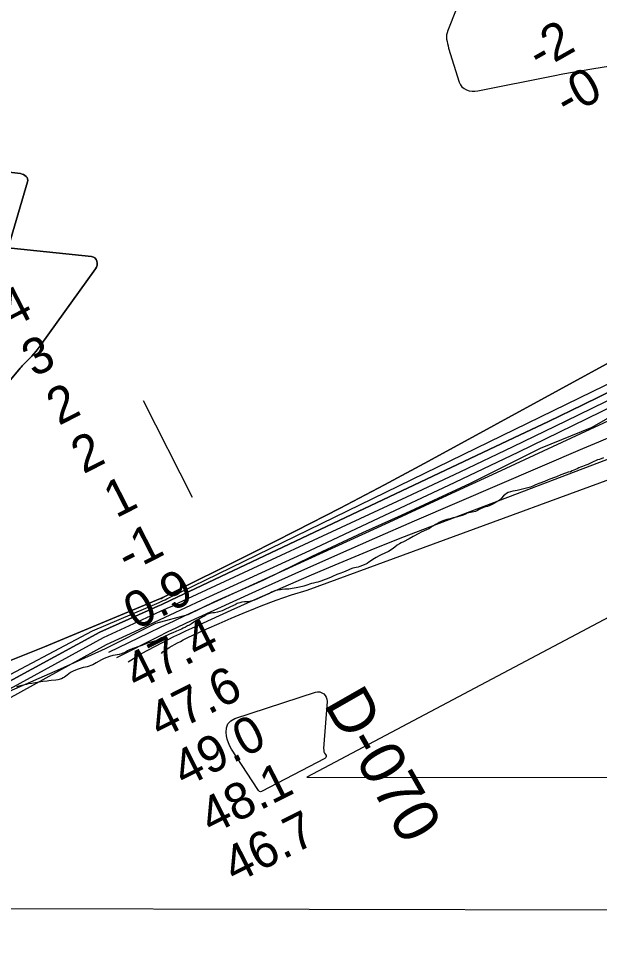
# Model space of a CAD drawing. Extents: x 3177385 to 3215275, y 903885 to 929304.
# Drawn here: x 3190624 to 3191696, y 909264 to 910956 of the extents above; entities that cross this region are included whole.
import ezdxf

# ---------------------------------------------------------------- set-up
doc = ezdxf.new("R2010")
doc.units = 0
for name, color, linetype in [('V-GRID-FRAM', 7, 'Continuous'), ('V-RIVR-EDGE', 7, 'Continuous'), ('V-RIVR-RANG', 7, 'Continuous'), ('V-RIVR-RANG-IDEN', 7, 'Continuous'), ('V-SITE-VEGE', 7, 'Continuous'), ('V-TOPO-BNDY', 7, 'Continuous'), ('V-TOPO-DPTH', 7, 'Continuous'), ('V-TOPO-MAJR', 7, 'Continuous'), ('V-TOPO-MINR', 7, 'Continuous'), ('V-TOPO-WATR', 7, 'Continuous')]:
    doc.layers.add(name, color=color, linetype=linetype)

msp = doc.modelspace()

# ---------------------------------------------------------------- linework, layer by layer
at = {"layer": 'V-GRID-FRAM'}
msp.add_lwpolyline([(3181653.7, 927525.9), (3181603.5, 909337.1), (3212939.2, 909264.2), (3212973.6, 927453), (3181653.7, 927525.9)], dxfattribs=at)
at = {"layer": 'V-RIVR-EDGE'}
msp.add_lwpolyline([(3190607.3, 909716.4), (3190701.7, 909757.9), (3190784.4, 909795), (3190877.1, 909841.8), (3190936.7, 909857.7), (3190985.9, 909881.5), (3191075.1, 909921.2), (3191165.2, 909965.4), (3191259.2, 910008.6), (3191330.1, 910041), (3191457.2, 910099.8), (3191586.4, 910164.3), (3191682.1, 910203.2), (3191755.7, 910245.6)], dxfattribs=at)
at = {"layer": 'V-RIVR-RANG'}
msp.add_line((3190945, 910073.2), (3190854.6, 910251.6), dxfattribs=at)
at = {"layer": 'V-SITE-VEGE'}
for p, q in [((3191684.8, 910139.7), (3191673.8, 910134)), ((3191688.1, 910141.1), (3191684.8, 910139.7)), ((3191691.7, 910142.6), (3191688.1, 910141.1)), ((3191695.6, 910143.6), (3191691.7, 910142.6)), ((3191702.9, 910146.5), (3191695.6, 910143.6)), ((3191632.8, 910118.1), (3191624.2, 910114.8)), ((3191637.5, 910119.7), (3191632.8, 910118.1)), ((3191641.6, 910120.9), (3191637.5, 910119.7)), ((3191644.9, 910122.2), (3191641.6, 910120.9)), ((3191654, 910126.1), (3191644.9, 910122.2)), ((3191657.1, 910127.8), (3191654, 910126.1)), ((3191660.4, 910129.3), (3191657.1, 910127.8)), ((3191664.1, 910130.5), (3191660.4, 910129.3)), ((3191670.1, 910133), (3191664.1, 910130.5)), ((3191671.8, 910133.4), (3191670.1, 910133)), ((3191673.8, 910134), (3191671.8, 910133.4)), ((3191593.9, 910102.7), (3191585.3, 910099.6)), ((3191600.9, 910105.9), (3191593.9, 910102.7)), ((3191604, 910106.9), (3191600.9, 910105.9)), ((3191612.4, 910110.2), (3191604, 910106.9)), ((3191616.3, 910111.4), (3191612.4, 910110.2)), ((3191624.2, 910114.8), (3191616.3, 910111.4)), ((3191535.8, 910084.8), (3191527, 910082.3)), ((3191540, 910085.8), (3191535.8, 910084.8)), ((3191543.5, 910086.3), (3191540, 910085.8)), ((3191551, 910088.2), (3191543.5, 910086.3)), ((3191567.9, 910092.6), (3191551, 910088.2)), ((3191573.4, 910094.7), (3191567.9, 910092.6)), ((3191577.6, 910096.5), (3191573.4, 910094.7)), ((3191585.3, 910099.6), (3191577.6, 910096.5)), ((3191509.2, 910067.4), (3191505, 910064.9)), ((3191511.9, 910069.3), (3191509.2, 910067.4)), ((3191514.8, 910072.1), (3191511.9, 910069.3)), ((3191518.4, 910076.2), (3191514.8, 910072.1)), ((3191520.8, 910078.5), (3191518.4, 910076.2)), ((3191523.7, 910080.7), (3191520.8, 910078.5)), ((3191527, 910082.3), (3191523.7, 910080.7)), ((3191473.5, 910050.9), (3191470.6, 910049.2)), ((3191481.2, 910054.7), (3191473.5, 910050.9)), ((3191485.2, 910055.9), (3191481.2, 910054.7)), ((3191488.5, 910056.7), (3191485.2, 910055.9)), ((3191497.5, 910060.7), (3191488.5, 910056.7)), ((3191505, 910064.9), (3191497.5, 910060.7)), ((3191413.7, 910033), (3191406.3, 910030.5)), ((3191420.1, 910034.2), (3191413.7, 910033)), ((3191425.2, 910035.8), (3191420.1, 910034.2)), ((3191426.9, 910036), (3191425.2, 910035.8)), ((3191431.3, 910037), (3191426.9, 910036)), ((3191437.5, 910038.8), (3191431.3, 910037)), ((3191444, 910040.9), (3191437.5, 910038.8)), ((3191448, 910042.5), (3191444, 910040.9)), ((3191451.5, 910044.2), (3191448, 910042.5)), ((3191463.4, 910047), (3191451.5, 910044.2)), ((3191466.9, 910047.6), (3191463.4, 910047)), ((3191470.6, 910049.2), (3191466.9, 910047.6)), ((3191381.7, 910016.4), (3191379.1, 910014.9)), ((3191385.5, 910019), (3191381.7, 910016.4)), ((3191389.3, 910021.1), (3191385.5, 910019)), ((3191393, 910023.6), (3191389.3, 910021.1)), ((3191395.7, 910025.1), (3191393, 910023.6)), ((3191399.9, 910027), (3191395.7, 910025.1)), ((3191403.6, 910028.8), (3191399.9, 910027)), ((3191406.3, 910030.5), (3191403.6, 910028.8)), ((3191351.7, 910001.3), (3191344.2, 909996.9)), ((3191361.9, 910007), (3191351.7, 910001.3)), ((3191366.7, 910009.5), (3191361.9, 910007)), ((3191376.2, 910013.9), (3191366.7, 910009.5)), ((3191379.1, 910014.9), (3191376.2, 910013.9)), ((3191322.5, 909985.6), (3191317.7, 909982)), ((3191326.5, 909987.7), (3191322.5, 909985.6)), ((3191329.6, 909989.6), (3191326.5, 909987.7)), ((3191333.6, 909991.5), (3191329.6, 909989.6)), ((3191344.2, 909996.9), (3191333.6, 909991.5)), ((3191288.9, 909966), (3191283.2, 909962.8)), ((3191292.9, 909967.9), (3191288.9, 909966)), ((3191299.3, 909970.6), (3191292.9, 909967.9)), ((3191306.1, 909973.9), (3191299.3, 909970.6)), ((3191313, 909978.4), (3191306.1, 909973.9)), ((3191317.7, 909982), (3191313, 909978.4)), ((3191264.4, 909950.6), (3191253.4, 909946)), ((3191267.2, 909952), (3191264.4, 909950.6)), ((3191270.1, 909953.9), (3191267.2, 909952)), ((3191272.8, 909956.1), (3191270.1, 909953.9)), ((3191277.4, 909959.2), (3191272.8, 909956.1)), ((3191280.3, 909961.1), (3191277.4, 909959.2)), ((3191283.2, 909962.8), (3191280.3, 909961.1)), ((3191210.9, 909931.6), (3191202.7, 909927.9)), ((3191216.2, 909933.5), (3191210.9, 909931.6)), ((3191223.4, 909935.7), (3191216.2, 909933.5)), ((3191227.8, 909937.4), (3191223.4, 909935.7)), ((3191231.8, 909939.5), (3191227.8, 909937.4)), ((3191235.3, 909941.1), (3191231.8, 909939.5)), ((3191240.6, 909943), (3191235.3, 909941.1)), ((3191243.7, 909943.6), (3191240.6, 909943)), ((3191246.6, 909944.6), (3191243.7, 909943.6)), ((3191250.1, 909945.2), (3191246.6, 909944.6)), ((3191253.4, 909946), (3191250.1, 909945.2)), ((3191164.5, 909914.9), (3191153.9, 909911.2)), ((3191167.8, 909915.5), (3191164.5, 909914.9)), ((3191172.1, 909916.7), (3191167.8, 909915.5)), ((3191175.7, 909917.5), (3191172.1, 909916.7)), ((3191179.6, 909918.7), (3191175.7, 909917.5)), ((3191183.4, 909919.8), (3191179.6, 909918.7)), ((3191187.8, 909921.6), (3191183.4, 909919.8)), ((3191191.3, 909922.9), (3191187.8, 909921.6)), ((3191199, 909926), (3191191.3, 909922.9)), ((3191202.7, 909927.9), (3191199, 909926)), ((3191090.5, 909898.8), (3191086.8, 909896.7)), ((3191093.6, 909900.3), (3191090.5, 909898.8)), ((3191098.2, 909901.7), (3191093.6, 909900.3)), ((3191102.4, 909902.3), (3191098.2, 909901.7)), ((3191107, 909903), (3191102.4, 909902.3)), ((3191110.3, 909903.8), (3191107, 909903)), ((3191114.9, 909904.4), (3191110.3, 909903.8)), ((3191119.5, 909904.7), (3191114.9, 909904.4)), ((3191122.5, 909904.7), (3191119.5, 909904.7)), ((3191128.9, 909905.4), (3191122.5, 909904.7)), ((3191135.7, 909906.6), (3191128.9, 909905.4)), ((3191139.2, 909907.6), (3191135.7, 909906.6)), ((3191142.3, 909908.2), (3191139.2, 909907.6)), ((3191150.4, 909910.2), (3191142.3, 909908.2)), ((3191153.9, 909911.2), (3191150.4, 909910.2)), ((3191040.4, 909880.9), (3191036, 909880.3)), ((3191048.9, 909881.1), (3191040.4, 909880.9)), ((3191052.4, 909882.1), (3191048.9, 909881.1)), ((3191059, 909884.4), (3191052.4, 909882.1)), ((3191065.8, 909887.1), (3191059, 909884.4)), ((3191079.7, 909893.1), (3191065.8, 909887.1)), ((3191082.4, 909894.6), (3191079.7, 909893.1)), ((3191086.8, 909896.7), (3191082.4, 909894.6)), ((3190999.4, 909864.7), (3190995, 909863.5)), ((3191005.4, 909867.6), (3190999.4, 909864.7)), ((3191020.6, 909874.1), (3191005.4, 909867.6)), ((3191023.7, 909875.6), (3191020.6, 909874.1)), ((3191027, 909877.7), (3191023.7, 909875.6)), ((3191031.8, 909879.5), (3191027, 909877.7)), ((3191036, 909880.3), (3191031.8, 909879.5)), ((3190953, 909847.4), (3190949.4, 909845)), ((3190960.5, 909851.8), (3190953, 909847.4)), ((3190963.6, 909853.3), (3190960.5, 909851.8)), ((3190966.7, 909854.9), (3190963.6, 909853.3)), ((3190970.9, 909857.5), (3190966.7, 909854.9)), ((3190974.4, 909858.9), (3190970.9, 909857.5)), ((3190978.6, 909859.9), (3190974.4, 909858.9)), ((3190982.5, 909860.7), (3190978.6, 909859.9)), ((3190985.6, 909860.9), (3190982.5, 909860.7)), ((3190991.1, 909862.1), (3190985.6, 909860.9)), ((3190995, 909863.5), (3190991.1, 909862.1)), ((3190924.4, 909830.9), (3190915.4, 909827.2)), ((3190927.5, 909832.6), (3190924.4, 909830.9)), ((3190931.9, 909834.5), (3190927.5, 909832.6)), ((3190935.7, 909836.6), (3190931.9, 909834.5)), ((3190939.2, 909838.3), (3190935.7, 909836.6)), ((3190943.2, 909840.4), (3190939.2, 909838.3)), ((3190949.4, 909845), (3190943.2, 909840.4)), ((3190887.6, 909814.7), (3190881.7, 909811.3)), ((3190890.5, 909816.2), (3190887.6, 909814.7)), ((3190894.2, 909817.8), (3190890.5, 909816.2)), ((3190898.9, 909819.7), (3190894.2, 909817.8)), ((3190902.6, 909821.6), (3190898.9, 909819.7)), ((3190909.5, 909824.7), (3190902.6, 909821.6)), ((3190912.8, 909825.7), (3190909.5, 909824.7)), ((3190915.4, 909827.2), (3190912.8, 909825.7)), ((3190839, 909796.1), (3190835, 909794.8)), ((3190842.3, 909797.5), (3190839, 909796.1)), ((3190851.1, 909800.8), (3190842.3, 909797.5)), ((3190855.5, 909802.3), (3190851.1, 909800.8)), ((3190863.8, 909805.4), (3190855.5, 909802.3)), ((3190877.5, 909809.4), (3190863.8, 909805.4)), ((3190881.7, 909811.3), (3190877.5, 909809.4)), ((3190791.9, 909780.5), (3190787.1, 909778.8)), ((3190798.1, 909782.1), (3190791.9, 909780.5)), ((3190802.2, 909782.7), (3190798.1, 909782.1)), ((3190805.7, 909783.5), (3190802.2, 909782.7)), ((3190809.7, 909784), (3190805.7, 909783.5)), ((3190813.8, 909785), (3190809.7, 909784)), ((3190816.5, 909786.5), (3190813.8, 909785)), ((3190820.5, 909787.9), (3190816.5, 909786.5)), ((3190825.1, 909790.7), (3190820.5, 909787.9)), ((3190828.4, 909792.4), (3190825.1, 909790.7)), ((3190832.2, 909793.6), (3190828.4, 909792.4)), ((3190835, 909794.8), (3190832.2, 909793.6)), ((3190761.2, 909765.2), (3190750.5, 909761.5)), ((3190767.2, 909768.6), (3190761.2, 909765.2)), ((3190776.7, 909774.5), (3190767.2, 909768.6)), ((3190782, 909776.5), (3190776.7, 909774.5)), ((3190787.1, 909778.8), (3190782, 909776.5)), ((3190713.7, 909746.1), (3190708.8, 909742.3)), ((3190719.6, 909750.6), (3190713.7, 909746.1)), ((3190722.3, 909752.3), (3190719.6, 909750.6)), ((3190725.8, 909753.9), (3190722.3, 909752.3)), ((3190733.8, 909757.3), (3190725.8, 909753.9)), ((3190743.2, 909759.9), (3190733.8, 909757.3)), ((3190747.4, 909760.9), (3190743.2, 909759.9)), ((3190750.5, 909761.5), (3190747.4, 909760.9)), ((3190638.6, 909728.9), (3190624.6, 909725.7)), ((3190641.5, 909730), (3190638.6, 909728.9)), ((3190648.3, 909730.7), (3190641.5, 909730)), ((3190651.3, 909731.3), (3190648.3, 909730.7)), ((3190655, 909731.6), (3190651.3, 909731.3)), ((3190659.2, 909732.6), (3190655, 909731.6)), ((3190662.3, 909733), (3190659.2, 909732.6)), ((3190665.4, 909733.8), (3190662.3, 909733)), ((3190669.1, 909734.4), (3190665.4, 909733.8)), ((3190677, 909735.1), (3190669.1, 909734.4)), ((3190680, 909735.3), (3190677, 909735.1)), ((3190684.4, 909736), (3190680, 909735.3)), ((3190692.9, 909736.9), (3190684.4, 909736)), ((3190696.4, 909737.5), (3190692.9, 909736.9)), ((3190703, 909739.4), (3190696.4, 909737.5)), ((3190706.1, 909740.8), (3190703, 909739.4)), ((3190708.8, 909742.3), (3190706.1, 909740.8)), ((3190624.6, 909725.7), (3190620, 909724.7)), ((3190007.3, 909317.5), (3195246.5, 909305.3))]:
    msp.add_line(p, q, dxfattribs=at)
at = {"layer": 'V-TOPO-BNDY'}
msp.add_lwpolyline([(3212104.8, 927455), (3211654.7, 925302.3), (3210557.1, 922651.3), (3209209.3, 920082.8), (3207894, 918536.9), (3206269, 917198.2), (3204190, 915875.2), (3202489, 914709.7), (3200914, 913922.2), (3198614.5, 912914.1), (3196094.5, 911748.6), (3194267.5, 911118.6), (3192913, 910488.6), (3191155.6, 909558.2), (3212939.7, 909531.5)], dxfattribs=at)
at = {"layer": 'V-TOPO-DPTH'}
for points in [[(3190594.8, 909767.6), (3190671.8, 909798.3), (3190886, 909887.1), (3190887.1, 909887.5), (3190890.2, 909889), (3191053.1, 909970.1), (3191135.3, 910011.6), (3191217.2, 910053.7), (3191298.6, 910096.7), (3191379.7, 910140.3), (3191862.2, 910403.3), (3191876.8, 910411.2), (3191891.4, 910419.1), (3191906, 910427.1), (3191920.6, 910435), (3192264.2, 910620.7), (3192356.7, 910671.1), (3192449, 910722), (3192540.9, 910773.5), (3192632.6, 910825.4), (3192780.4, 910909.7)], [(3192780.4, 910909.7), (3192632.6, 910825.4), (3192540.9, 910773.5), (3192449, 910722), (3192356.7, 910671.1), (3192264.2, 910620.7), (3191920.6, 910435), (3191906, 910427.1), (3191891.4, 910419.1), (3191876.8, 910411.2), (3191862.2, 910403.3), (3191379.7, 910140.3), (3191298.6, 910096.7), (3191217.2, 910053.7), (3191135.3, 910011.6), (3191053.1, 909970.1), (3190890.2, 909889), (3190887.1, 909887.5), (3190886, 909887.1), (3190671.8, 909798.3), (3190594.8, 909767.6)], [(3190773.8, 909825.2), (3190881.1, 909873.1), (3190887.1, 909875.7), (3190893, 909878.4), (3190898.9, 909881.2), (3190904.9, 909884), (3191537.1, 910183.1), (3191601, 910213.6), (3191664.9, 910244.3), (3191728.5, 910275.5), (3191792, 910306.9), (3191898.3, 910360), (3191908.5, 910365.1), (3191918.7, 910370.4), (3191928.8, 910375.8), (3191938.9, 910381.2), (3192121.7, 910481.7), (3192222.9, 910537.8), (3192324, 910594.2), (3192424.7, 910651.3), (3192525.2, 910708.7), (3192802.3, 910868.1)], [(3192802.3, 910868.1), (3192525.2, 910708.7), (3192424.7, 910651.3), (3192324, 910594.2), (3192222.9, 910537.8), (3192121.7, 910481.7), (3191938.9, 910381.2), (3191928.8, 910375.8), (3191918.7, 910370.4), (3191908.5, 910365.1), (3191898.3, 910360), (3191792, 910306.9), (3191728.5, 910275.5), (3191664.9, 910244.3), (3191601, 910213.6), (3191537.1, 910183.1), (3190904.9, 909884), (3190898.9, 909881.2), (3190893, 909878.4), (3190887.1, 909875.7), (3190881.1, 909873.1), (3190773.8, 909825.2)], [(3189907.8, 909317.8), (3190786.5, 909802.2), (3190846.3, 909830.4), (3190875, 909843.9), (3190903.7, 909857.3), (3190932.5, 909870.7), (3190961.3, 909884), (3191160.9, 909975.9), (3191289.3, 910035.6), (3191417.5, 910095.9), (3191545.2, 910157.1), (3191672.6, 910218.8), (3191886.8, 910323.6), (3191909.6, 910334.9), (3191932.2, 910346.4), (3191954.7, 910358.2), (3191977.1, 910370.2), (3192774.9, 910804.3)], [(3190485.7, 910687), (3190627.5, 910670.1), (3190630.4, 910669.4), (3190633.2, 910668.4), (3190635.7, 910666.9), (3190638, 910665), (3190639.7, 910662.7), (3190640.7, 910660.3), (3190641, 910657.7), (3190640.6, 910654.9), (3190605.9, 910537.4)], [(3190605.9, 910537.4), (3190640.6, 910654.9), (3190641, 910657.7), (3190640.7, 910660.3), (3190639.7, 910662.7), (3190638, 910665), (3190635.7, 910666.9), (3190633.2, 910668.4), (3190630.4, 910669.4), (3190627.5, 910670.1), (3190485.7, 910687)], [(3190610.2, 910532.5), (3190758.5, 910517.5), (3190762, 910516.4), (3190765, 910514.7), (3190767.1, 910512.1), (3190768.7, 910508.8), (3190769.2, 910505), (3190769, 910501.3), (3190767.8, 910497.8), (3190766, 910494.4), (3190664.2, 910352.9), (3190660.5, 910347.9), (3190656.6, 910343), (3190652.5, 910338.2), (3190648.3, 910333.6), (3190643.8, 910328.9), (3190641.7, 910326.7), (3190639.6, 910324.5), (3190637.4, 910322.4), (3190635.2, 910320.3), (3190633.1, 910318.1), (3190631, 910315.9), (3190629, 910313.7), (3190627, 910311.4), (3190486.2, 910142.7)], [(3190486.2, 910142.7), (3190627, 910311.4), (3190629, 910313.7), (3190631, 910315.9), (3190633.1, 910318.1), (3190635.2, 910320.3), (3190637.4, 910322.4), (3190639.6, 910324.5), (3190641.7, 910326.7), (3190643.8, 910328.9), (3190648.3, 910333.6), (3190652.5, 910338.2), (3190656.6, 910343), (3190660.5, 910347.9), (3190664.2, 910352.9), (3190766, 910494.4), (3190767.8, 910497.8), (3190769, 910501.3), (3190769.2, 910505), (3190768.7, 910508.8), (3190767.1, 910512.1), (3190765, 910514.7), (3190762, 910516.4), (3190758.5, 910517.5), (3190610.2, 910532.5)], [(3189840.3, 909317.9), (3190773.8, 909825.2)], [(3190773.8, 909825.2), (3189840.3, 909317.9)]]:
    msp.add_lwpolyline(points, dxfattribs=at)
at = {"layer": 'V-TOPO-MAJR'}
msp.add_lwpolyline([(3190826.3, 909770.5), (3190826.4, 909770.6), (3190850.9, 909785.9), (3190899.8, 909811.4), (3190910.6, 909816.9), (3190921.5, 909822.3), (3190932.5, 909827.6), (3190943.6, 909832.7), (3191016.4, 909865.8), (3191064, 909887.2), (3191111.8, 909908.3), (3191159.7, 909928.9), (3191207.8, 909949.2), (3191274.5, 909976.9), (3191330.7, 909999.4), (3191930.4, 910227.5)], dxfattribs=at)
at = {"layer": 'V-TOPO-MINR'}
for points in [[(3191462.9, 911053.6), (3191415.4, 910933.7), (3191414.2, 910929.8), (3191413.4, 910925.8), (3191413.2, 910921.8), (3191413.5, 910917.7), (3191414.2, 910913.6), (3191415, 910909.6), (3191416, 910905.5), (3191417.1, 910901.5), (3191436.7, 910838.7), (3191438.9, 910834), (3191441.7, 910830), (3191445.6, 910826.8), (3191450, 910824.3), (3191455.2, 910822.8), (3191460.3, 910821.8), (3191465.6, 910821.8), (3191470.9, 910822.4), (3191610.1, 910850.5), (3191627.7, 910854), (3191645.4, 910857.2), (3191663.1, 910860.3), (3191680.9, 910863.2), (3191731.2, 910871)], [(3190594.8, 909767.6), (3190671.8, 909798.3), (3190886, 909887.1), (3190887.1, 909887.5), (3190890.2, 909889), (3191053.1, 909970.1), (3191135.3, 910011.6), (3191217.2, 910053.7), (3191298.6, 910096.7), (3191379.7, 910140.3), (3191862.2, 910403.3), (3191876.8, 910411.2), (3191891.4, 910419.1), (3191906, 910427.1), (3191920.6, 910435), (3192264.2, 910620.7), (3192356.7, 910671.1), (3192449, 910722), (3192540.9, 910773.5), (3192632.6, 910825.4), (3192780.4, 910909.7)], [(3189797.7, 909318), (3190760.6, 909827.6), (3190883.5, 909880.1), (3190887.1, 909881.7), (3190890.6, 909883.3), (3190894.1, 909884.9), (3190897.5, 909886.5), (3191753.1, 910303.1), (3191779.7, 910316.1), (3191806.3, 910329.2), (3191832.7, 910342.4), (3191859.2, 910355.6), (3191903.9, 910378.2), (3191908, 910380.2), (3191912, 910382.3), (3191916, 910384.5), (3191920, 910386.7), (3191991, 910425.7), (3192030.3, 910447.6), (3192069.6, 910469.7), (3192108.8, 910492), (3192147.8, 910514.5), (3192771.7, 910876.7)], [(3189907.8, 909317.8), (3190786.5, 909802.2), (3190846.3, 909830.4), (3190875, 909843.9), (3190903.7, 909857.3), (3190932.5, 909870.7), (3190961.3, 909884), (3191160.9, 909975.9), (3191289.3, 910035.6), (3191417.5, 910095.9), (3191545.2, 910157.1), (3191672.6, 910218.8), (3191886.8, 910323.6), (3191909.6, 910334.9), (3191932.2, 910346.4), (3191954.7, 910358.2), (3191977.1, 910370.2), (3192774.9, 910804.3)], [(3189871.8, 909317.8), (3190780.5, 909815.1), (3190876.4, 909859.3), (3190887.1, 909864.2), (3190897.8, 909869.1), (3190908.4, 909874), (3190919.1, 909879), (3191340, 910074.6), (3191438.2, 910120.7), (3191536.1, 910167.2), (3191633.7, 910214.4), (3191731.1, 910262.1), (3191892.6, 910341.8), (3191909, 910350.1), (3191925.4, 910358.5), (3191941.7, 910367.1), (3191957.8, 910375.8), (3192458.3, 910650.3), (3192523.5, 910686.3), (3192588.6, 910722.5), (3192653.5, 910759)], [(3190485.7, 910687), (3190627.5, 910670.1), (3190630.4, 910669.4), (3190633.2, 910668.4), (3190635.7, 910666.9), (3190638, 910665), (3190639.7, 910662.7), (3190640.7, 910660.3), (3190641, 910657.7), (3190640.6, 910654.9), (3190605.9, 910537.4)], [(3190790.6, 909788.1), (3190864.2, 909823.8), (3190886.9, 909834.8), (3190909.7, 909845.6), (3190932.6, 909856.2), (3190955.5, 909866.8), (3191108.6, 909936.7), (3191208.1, 909982.3), (3191307.6, 910027.9), (3191406.9, 910073.7), (3191506.2, 910119.6), (3191875.4, 910290.7), (3191910.3, 910306.9), (3191945.2, 910323.2), (3191980.1, 910339.5), (3192014.9, 910355.9), (3192042.6, 910369), (3192091.4, 910391.8), (3192140.3, 910414.4), (3192189.3, 910436.6), (3192238.4, 910458.6), (3192563.6, 910602.6), (3192609.9, 910623.1), (3192656.1, 910643.7)], [(3190610.2, 910532.5), (3190758.5, 910517.5), (3190762, 910516.4), (3190765, 910514.7), (3190767.1, 910512.1), (3190768.7, 910508.8), (3190769.2, 910505), (3190769, 910501.3), (3190767.8, 910497.8), (3190766, 910494.4), (3190664.2, 910352.9), (3190660.5, 910347.9), (3190656.6, 910343), (3190652.5, 910338.2), (3190648.3, 910333.6), (3190643.8, 910328.9), (3190641.7, 910326.7), (3190639.6, 910324.5), (3190637.4, 910322.4), (3190635.2, 910320.3), (3190633.1, 910318.1), (3190631, 910315.9), (3190629, 910313.7), (3190627, 910311.4), (3190486.2, 910142.7)], [(3190887.5, 909785.7), (3190890.4, 909788.8), (3190901.6, 909797), (3190917.3, 909805.6), (3190922.4, 909808.2), (3190927.4, 909810.8), (3190932.5, 909813.3), (3190937.6, 909815.7), (3190971.5, 909831.1), (3190993.7, 909841), (3191015.9, 909850.7), (3191038.3, 909860.2), (3191060.8, 909869.4), (3191071.4, 909873.7), (3191099.4, 909884.4), (3191127.6, 909894.2), (3191156.3, 909902.8), (3191984.1, 910205.7)], [(3190805, 909778.8), (3190882.1, 909817.5), (3190898.8, 909825.7), (3190915.7, 909833.9), (3190932.6, 909841.9), (3190949.6, 909849.7), (3191061.3, 909900.6), (3191134.4, 909933.5), (3191207.5, 909966.1), (3191280.9, 909998.3), (3191354.4, 910030.1), (3191664.6, 910163.4), (3191693.9, 910175.8), (3191723.3, 910187.9)], [(3191010.1, 909656.4), (3191015.6, 909662), (3191022.9, 909666.4), (3191171.4, 909714.5), (3191175.4, 909715.1), (3191179.4, 909715), (3191183.1, 909713.7), (3191186.7, 909711.7), (3191189.5, 909708.7), (3191191.6, 909705.4), (3191192.6, 909701.6), (3191192.9, 909697.4), (3191186.5, 909610.6), (3191186.7, 909607.7), (3191187.2, 909604.9), (3191188.5, 909602.3), (3191190.2, 909599.9), (3191191.1, 909597.8), (3191191.3, 909595.8), (3191190.4, 909594), (3191188.8, 909592.4), (3191072.3, 909531.4), (3191070.1, 909531), (3191068.1, 909531.8), (3191066.3, 909533.5), (3191065, 909535.3), (3191017, 909609.4), (3191013.7, 909615.3), (3191011, 909621.4), (3191009, 909627.8), (3191007.7, 909634.4), (3191006.8, 909640.6), (3191007.5, 909649.1), (3191010.1, 909656.4)]]:
    msp.add_lwpolyline(points, dxfattribs=at)
at = {"layer": 'V-TOPO-WATR'}
for points in [[(3190773.8, 909825.2), (3190881.1, 909873.1), (3190887.1, 909875.7), (3190893, 909878.4), (3190898.9, 909881.2), (3190904.9, 909884), (3191537.1, 910183.1), (3191601, 910213.6), (3191664.9, 910244.3), (3191728.5, 910275.5), (3191792, 910306.9), (3191898.3, 910360), (3191908.5, 910365.1), (3191918.7, 910370.4), (3191928.8, 910375.8), (3191938.9, 910381.2), (3192121.7, 910481.7), (3192222.9, 910537.8), (3192324, 910594.2), (3192424.7, 910651.3), (3192525.2, 910708.7), (3192802.3, 910868.1)], [(3189840.3, 909317.9), (3190773.8, 909825.2)]]:
    msp.add_lwpolyline(points, dxfattribs=at)

# ---------------------------------------------------------------- texts
at = {"layer": 'V-RIVR-RANG'}
for s, rotation, p in [('-2', 29.5319, (3191585.3, 910858.7)), ('-0', 29.5319, (3191635.9, 910772.4)), ('4', 27.0992, (3190610.2, 910384.7)), ('3', 27.0992, (3190652.5, 910294)), ('2', 27.0992, (3190698.3, 910205.1)), ('2', 27.0992, (3190743.6, 910115.9)), ('1', 27.0992, (3190803.7, 910034.4)), ('-1', 27.0992, (3190825.6, 909933.2)), ('0.9', 27.0992, (3190840.4, 909828.5)), ('47.4', 26.8183, (3190841.6, 909717.4)), ('47.6', 26.8183, (3190885.3, 909627.5)), ('49.0', 26.8183, (3190929.7, 909537.9)), ('48.1', 26.8183, (3190979.8, 909451.1)), ('46.7', 26.8183, (3191023, 909360.9))]:
    msp.add_text(s, height=67, rotation=rotation, dxfattribs=at).set_placement(p)
at = {"layer": 'V-RIVR-RANG-IDEN'}
msp.add_text('D-070', height=83, rotation=299.688, dxfattribs=at).set_placement((3191185.9, 909692.7))

doc.saveas('drawing.dxf')
